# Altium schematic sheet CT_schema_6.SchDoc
size 297 x 173 mm
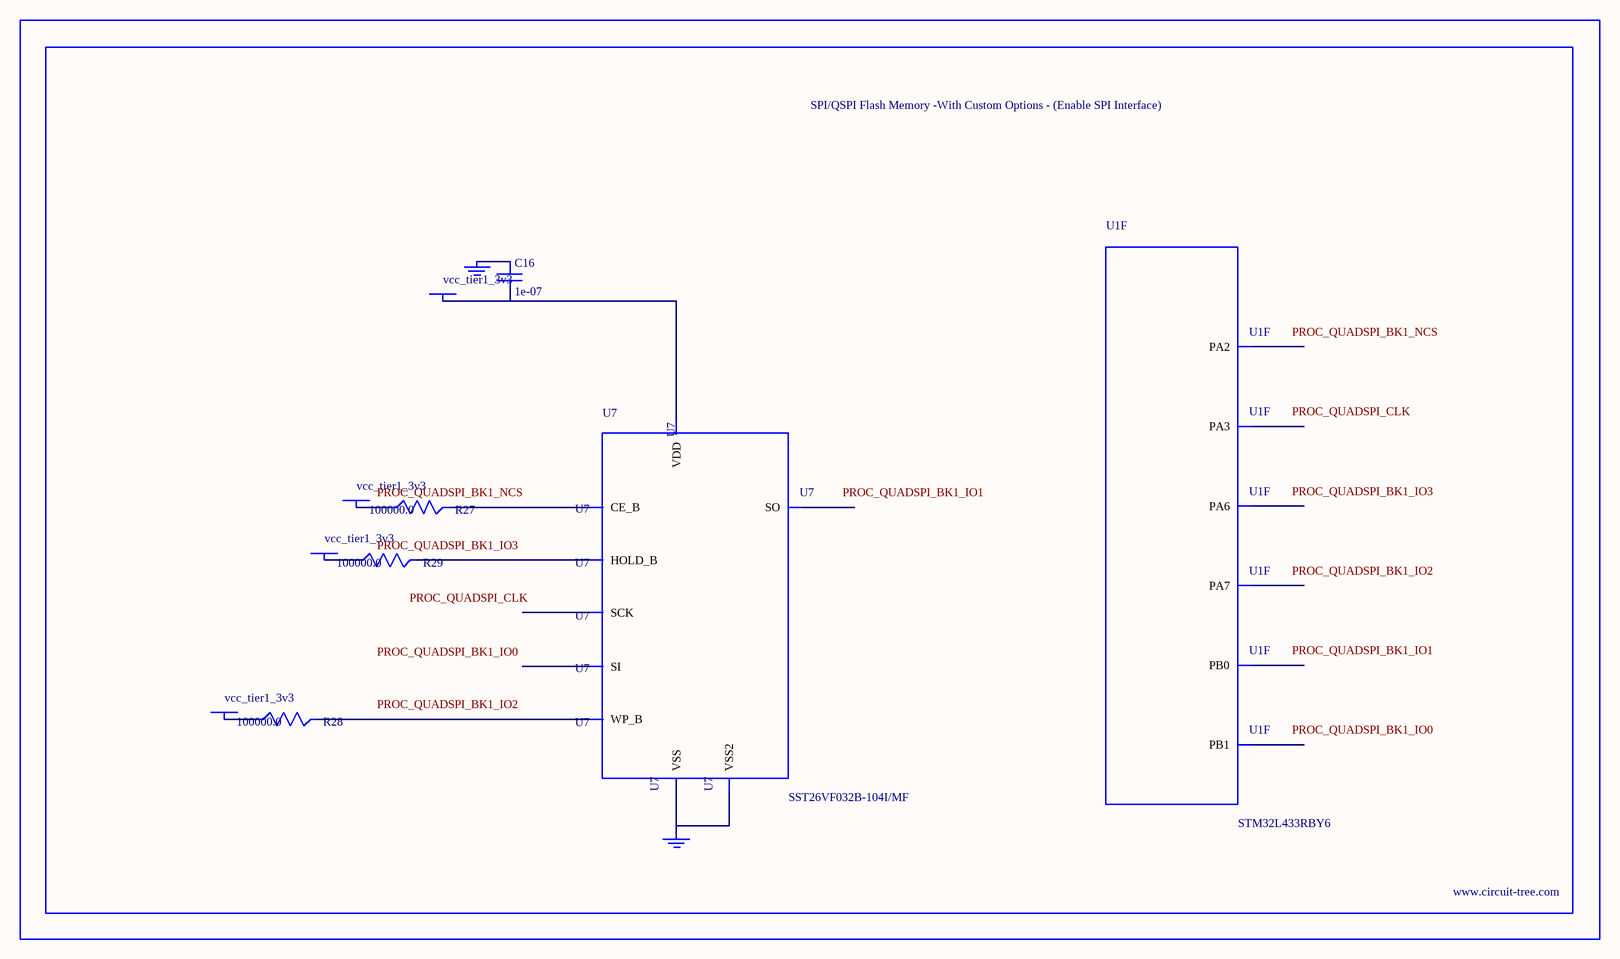
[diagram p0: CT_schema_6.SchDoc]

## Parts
BORDER5  (no value)
C16  1e-07  [C0402]
GND_INSTANCE_5_0  (no value)
GND_INSTANCE_5_1  (no value)
POWER_INSTANCE_5_0  vcc_tier1_3v3
POWER_INSTANCE_5_1  vcc_tier1_3v3
POWER_INSTANCE_5_2  vcc_tier1_3v3
POWER_INSTANCE_5_3  vcc_tier1_3v3
R27  100000.0  [R0603]
R28  100000.0  [R0603]
R29  100000.0  [R0603]
U1  STM32L433RBY6  [WLCSP64]  (part F of 6)
U7  SST26VF032B-104I/MF  [WFDN-8]

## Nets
NetC16_1: C16.1 GND_INSTANCE_5_0.0(GND)
NetC16_2: C16.2 POWER_INSTANCE_5_3.0(PWR) U7.8(VDD)
NetGND_INSTANCE_5_1_0: GND_INSTANCE_5_1.0(GND) U7.4(VSS) U7.9(VSS2)
NetPOWER_INSTANCE_5_0_0: POWER_INSTANCE_5_0.0(PWR) R27.1
NetPOWER_INSTANCE_5_1_0: POWER_INSTANCE_5_1.0(PWR) R28.1
NetPOWER_INSTANCE_5_2_0: POWER_INSTANCE_5_2.0(PWR) R29.1
NetR27_2: R27.2 U7.1(CE_B)
NetR28_2: R28.2 U7.3(WP_B)
NetR29_2: R29.2 U7.7(HOLD_B)

Not connected (* = marked no-connect by the designer): U1 F4(PB0) F6(PA2) G5(PA6) G6(PA3) H5(PB1) H6(PA7); U7 2(SO) 5(SI) 6(SCK)

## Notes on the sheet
- Labels drawn without touching a wire or pin: PROC_QUADSPI_BK1_IO0, PROC_QUADSPI_BK1_IO1, PROC_QUADSPI_BK1_IO2, PROC_QUADSPI_BK1_IO3, PROC_QUADSPI_BK1_NCS, PROC_QUADSPI_CLK

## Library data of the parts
BORDER5 = BORDER_PAGE5
C16 = C0402C104K3RACTU
GND_INSTANCE_5_0 GND_INSTANCE_5_1 = GND
POWER_INSTANCE_5_0-POWER_INSTANCE_5_3 = PWR
R27-R29 = RC0603JR-07100KL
